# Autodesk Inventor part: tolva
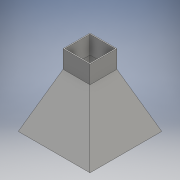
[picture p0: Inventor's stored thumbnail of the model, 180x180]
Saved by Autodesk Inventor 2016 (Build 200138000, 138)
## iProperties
Created: 2016-06
Part Number: tolva
Material: Genérico
Document SubType Name: Modeling
Designer: adm
Density: 1 g/cm^3
Appearance: Valor por defecto
Author: adm
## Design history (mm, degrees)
sketch "Boceto1"
  geometry: L1 (-40, -40)-(40, -40); L2 (40, -40)-(40, 40); L3 (40, 40)-(-40, 40); L4 (-40, 40)-(-40, -40); L5 (-40, -40)-(40, 40); L6 (40, -40)-(-40, 40); 1 further point
  constraints: 12 end point, 2 midpoint, 2 parallel, 1 horizontal, 1 perpendicular
  dimensions: "d0" = 80 distance of L3.end L2.end; "d1" = 80 distance of L2.end L1.end
node "Plano de trabajo1"
sketch "Boceto2"
  geometry: L1 (-15, -15)-(15, -15); L2 (15, -15)-(15, 15); L3 (15, 15)-(-15, 15); L4 (-15, 15)-(-15, -15); L5 (-15, -15)-(15, 15); L6 (15, -15)-(-15, 15); 1 further point
  constraints: 12 end point, 2 midpoint, 2 parallel, 1 horizontal, 1 perpendicular
  dimensions: "d3" = 30 distance of L3.end L2.end; "d4" = 30 distance of L2.end L1.end
feature "Solevación1" sketch "Boceto2" dims "d5" = 0, "d6" = 90 deg, "d7" = 0, "d8" = 90 deg
sketch "Boceto3"
  geometry: L1 (30, 30)-(0, 30) reference; L2 (0, 0)-(30, 0); L3 (30, 0)-(30, 30); L4 (30, 30)-(0, 30); L5 (0, 30)-(0, 0); L6 (0, 0)-(30, 30); L7 (30, 0)-(0, 30); 1 further point
  constraints: 12 end point, 2 midpoint, 2 parallel, 1 horizontal, 1 perpendicular
  dimensions: "d9" = 30 distance of L4.end L1.start (derived); "d10" = 30 distance of L1.start L2.end (derived)
extrude "Extrusión1" join sketch "Boceto3" distance "d11" = 20; taper "d12" = 0 deg
feature "Vaciado1" dims "d13" = 1
node "Sólido1"
